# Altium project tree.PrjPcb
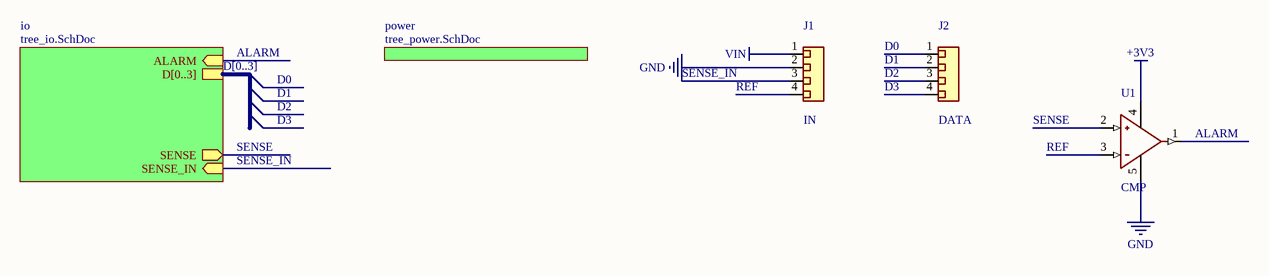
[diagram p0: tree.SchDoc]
4 sheets, 12 parts. Net scope: hierarchical (ports join the sheet entries above them; power ports are global).
Sheets:
  tree.SchDoc
    io = tree_io.SchDoc
      leds = tree_io.leds.SchDoc
    power = tree_power.SchDoc

## Sheet tree.SchDoc
size A4

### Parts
J1  IN  [HDR1X4]
J2  DATA  [HDR1X4]
U1  CMP  [SOT23-5]

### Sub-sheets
io = tree_io.SchDoc: ALARM (in), D[0..3], SENSE (out), SENSE_IN (in)
power = tree_power.SchDoc: no entries

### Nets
+3V3: U1.4(V+)
GND: J1.2(Passive) U1.5(V-)
VIN: J1.1(Passive)
ALARM: U1.1 ; sheet io/ALARM
D0: J2.1(Passive)
D1: J2.2(Passive)
D2: J2.3(Passive)
D3: J2.4(Passive)
REF: J1.4(Passive) U1.3(-)
SENSE: U1.2(+) ; sheet io/SENSE
SENSE_IN: J1.3(Passive) ; sheet io/SENSE_IN

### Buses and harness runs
bus D[0..3] = sheet io/D[0..3]

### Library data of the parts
J1 J2 = Connector_4
U1 = Comparator

## Sheet tree_io.SchDoc
size A4
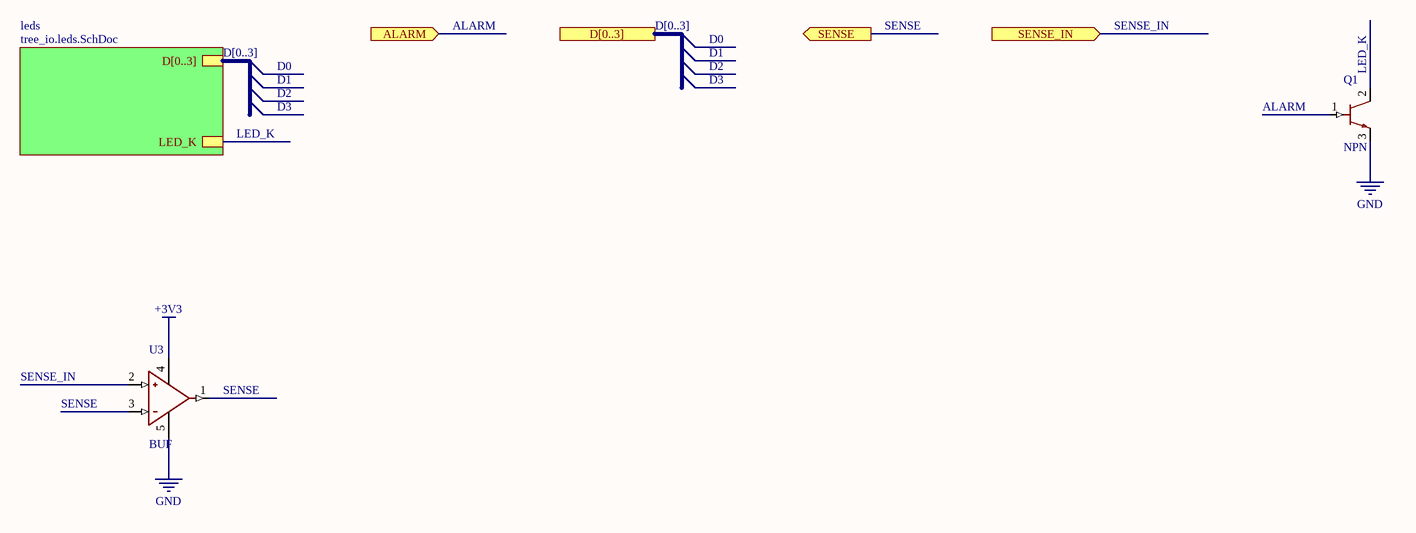
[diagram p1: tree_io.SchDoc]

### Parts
Q1  NPN  [SOT23]
U3  BUF  [SOT23-5]

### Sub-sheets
leds = tree_io.leds.SchDoc: D[0..3], LED_K

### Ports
ALARM (in), D[0..3], SENSE (out), SENSE_IN (in)

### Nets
+3V3: U3.4(V+)
GND: Q1.3(E) U3.5(V-)
ALARM: Q1.1(B) ; port ALARM
LED_K: Q1.2(C) ; sheet leds/LED_K
SENSE: U3.1 U3.3(-) ; port SENSE
SENSE_IN: U3.2(+) ; port SENSE_IN

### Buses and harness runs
bus D[0..3] = port D[0..3]
bus D[0..3] = sheet leds/D[0..3]

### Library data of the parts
Q1 = BJT_NPN
U3 = Operational_Amplifier

## Sheet tree_io.leds.SchDoc
size A4
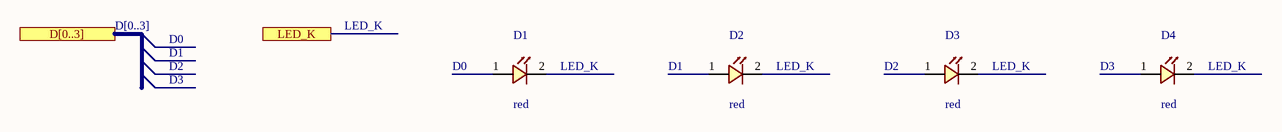
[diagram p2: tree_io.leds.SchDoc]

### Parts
D1  red  [LED0603]
D2  red  [LED0603]
D3  red  [LED0603]
D4  red  [LED0603]

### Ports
D[0..3], LED_K

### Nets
D0: D1.1(A)
D1: D2.1(A)
D2: D3.1(A)
D3: D4.1(A)
LED_K: D1.2(K) D2.2(K) D3.2(K) D4.2(K) ; port LED_K

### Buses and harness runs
bus D[0..3] = port D[0..3]

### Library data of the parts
D1-D4 = LED

## Sheet tree_power.SchDoc
size A4
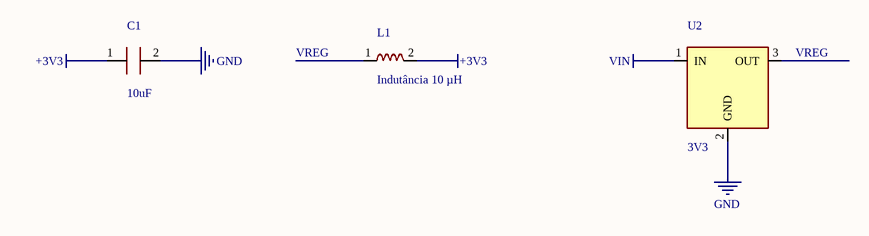
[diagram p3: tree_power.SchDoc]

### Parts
C1  10uF  [C0603]
L1  Indutância 10 µH  [L0805]
U2  3V3  [SOT223]

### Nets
+3V3: C1.1(A) L1.2(B)
GND: C1.2(B) U2.2(GND)
VIN: U2.1(IN)
VREG: L1.1(A) U2.3(OUT)

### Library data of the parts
C1 = Capacitor: MPN: X-1; Note: tolerância ±10 %
L1 = Inductor
U2 = Linear_Regulator

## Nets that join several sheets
+3V3: tree (U1.4), tree_io (U3.4), tree_power (C1.1 L1.2)
GND: tree (J1.2 U1.5), tree_io (Q1.3 U3.5), tree_power (C1.2 U2.2)
VIN: tree (J1.1), tree_power (U2.1)
ALARM: tree (U1.1), tree_io (Q1.1)
D0: tree (J2.1), tree_io.leds (D1.1)
D1: tree (J2.2), tree_io.leds (D2.1)
D2: tree (J2.3), tree_io.leds (D3.1)
D3: tree (J2.4), tree_io.leds (D4.1)
LED_K: tree_io (Q1.2), tree_io.leds (D1.2 D2.2 D3.2 D4.2)
SENSE: tree (U1.2), tree_io (U3.1 U3.3)
SENSE_IN: tree (J1.3), tree_io (U3.2)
